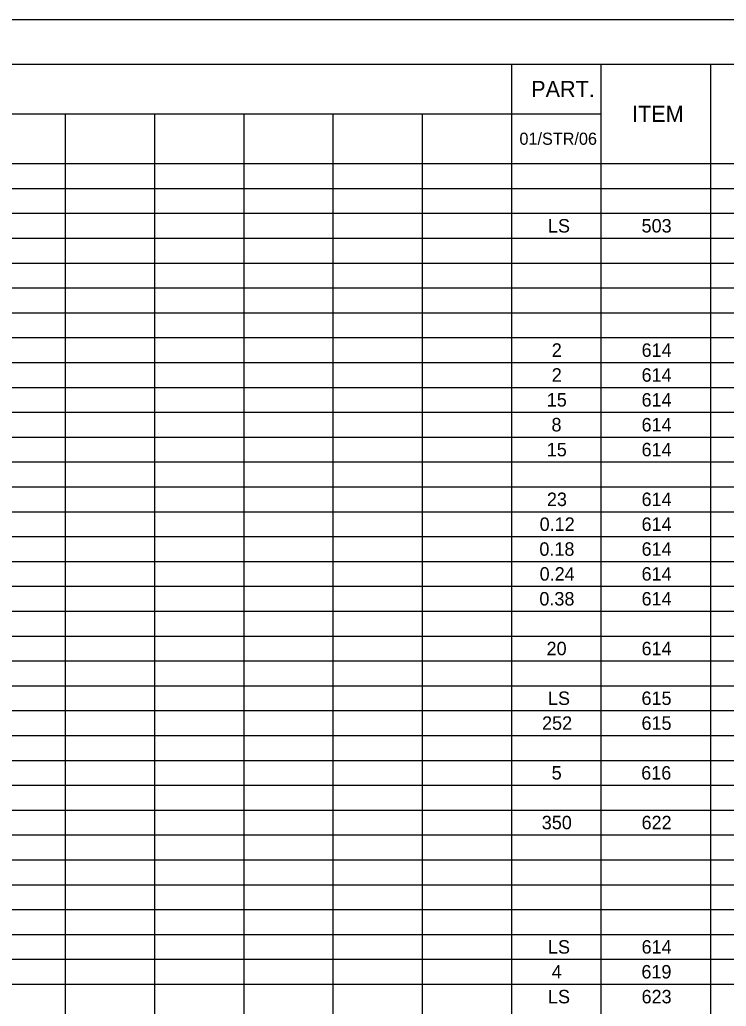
# Model space of a CAD drawing. Extents: x 0 to 34, y 0 to 22.
# Drawn here: x 9.03 to 16.97, y 10.89 to 22 of the extents above; entities that cross this region are included whole.
import ezdxf

# ---------------------------------------------------------------- set-up
doc = ezdxf.new("R2010")
doc.units = 0
for name, color, linetype in [('Default', 7, 'Continuous'), ('SH_Border', 7, 'Continuous'), ('SH_Cut_Line', 7, 'Continuous')]:
    doc.layers.add(name, color=color, linetype=linetype)

msp = doc.modelspace()

# ---------------------------------------------------------------- linework, layer by layer
at = {"layer": 'Default'}
for p, q in [((1.5, 21.5), (32, 21.5)), ((14.56, 21.5), (14.56, 0.5)), ((15.564, 21.5), (15.564, 0.5)), ((16.799, 21.5), (16.799, 0.5)), ((1.5, 20.94), (15.564, 20.94)), ((9.537, 20.94), (9.537, 0.5)), ((10.541, 20.94), (10.541, 0.5)), ((11.546, 20.94), (11.546, 0.5)), ((12.55, 20.94), (12.55, 0.5)), ((13.555, 20.94), (13.555, 0.5)), ((1.5, 20.38), (32, 20.38)), ((1.5, 20.1), (32, 20.1)), ((1.5, 19.82), (32, 19.82)), ((1.5, 19.54), (32, 19.54)), ((1.5, 19.26), (32, 19.26)), ((1.5, 18.98), (32, 18.98)), ((1.5, 18.7), (32, 18.7)), ((1.5, 18.42), (32, 18.42)), ((1.5, 18.14), (32, 18.14)), ((1.5, 17.86), (32, 17.86)), ((1.5, 17.58), (32, 17.58)), ((1.5, 17.3), (32, 17.3)), ((1.5, 17.02), (32, 17.02)), ((1.5, 16.74), (32, 16.74)), ((1.5, 16.46), (32, 16.46)), ((1.5, 16.18), (32, 16.18)), ((1.5, 15.9), (32, 15.9)), ((1.5, 15.62), (32, 15.62)), ((1.5, 15.34), (32, 15.34)), ((1.5, 15.06), (32, 15.06)), ((1.5, 14.78), (32, 14.78)), ((1.5, 14.5), (32, 14.5)), ((1.5, 14.22), (32, 14.22)), ((1.5, 13.94), (32, 13.94)), ((1.5, 13.66), (32, 13.66)), ((1.5, 13.38), (32, 13.38)), ((1.5, 13.1), (32, 13.1)), ((1.5, 12.82), (32, 12.82)), ((1.5, 12.54), (32, 12.54)), ((1.5, 12.26), (32, 12.26)), ((1.5, 11.98), (32, 11.98)), ((1.5, 11.7), (32, 11.7)), ((1.5, 11.42), (32, 11.42)), ((1.5, 11.14), (32, 11.14))]:
    msp.add_line(p, q, dxfattribs=at)
at = {"layer": 'SH_Border'}
msp.add_lwpolyline([(1.5, 21.5), (33.5, 21.5), (33.5, 0.5), (1.5, 0.5)], close=True, dxfattribs=at)
at = {"layer": 'SH_Cut_Line'}
msp.add_lwpolyline([(0, 0), (34, 0), (34, 22), (0, 22)], close=True, dxfattribs=at)

# ---------------------------------------------------------------- texts
at = {"layer": 'Default'}
for s, height, p in [('PART.', 0.1818, (14.78, 21.129)), ('ITEM', 0.1818, (15.915, 20.849)), ('01/STR/06', 0.1364, (14.648, 20.592)), ('LS', 0.1515, (14.969, 19.604)), ('503', 0.1515, (16.022, 19.604)), ('2', 0.152, (15.011, 18.204)), ('614', 0.1515, (16.022, 18.204)), ('2', 0.152, (15.011, 17.924)), ('614', 0.1515, (16.022, 17.924)), ('15', 0.1515, (14.955, 17.644)), ('614', 0.1515, (16.022, 17.644)), ('8', 0.152, (15.008, 17.364)), ('614', 0.1515, (16.022, 17.364)), ('15', 0.1515, (14.955, 17.084)), ('614', 0.1515, (16.022, 17.084)), ('23', 0.1515, (14.957, 16.524)), ('614', 0.1515, (16.022, 16.524)), ('0.12', 0.1515, (14.875, 16.244)), ('614', 0.1515, (16.022, 16.244)), ('0.18', 0.1515, (14.872, 15.964)), ('614', 0.1515, (16.022, 15.964)), ('0.24', 0.1515, (14.875, 15.684)), ('614', 0.1515, (16.022, 15.684)), ('0.38', 0.1515, (14.872, 15.404)), ('614', 0.1515, (16.022, 15.404)), ('20', 0.1515, (14.953, 14.844)), ('614', 0.1515, (16.022, 14.844)), ('LS', 0.1515, (14.969, 14.284)), ('615', 0.1515, (16.021, 14.284)), ('252', 0.1515, (14.902, 14.004)), ('615', 0.1515, (16.021, 14.004)), ('5', 0.152, (15.01, 13.444)), ('616', 0.1515, (16.018, 13.444)), ('350', 0.1515, (14.899, 12.884)), ('622', 0.1515, (16.022, 12.884)), ('LS', 0.1515, (14.969, 11.484)), ('614', 0.1515, (16.022, 11.484)), ('4', 0.152, (15.011, 11.204)), ('619', 0.1515, (16.02, 11.204)), ('LS', 0.1515, (14.969, 10.924)), ('623', 0.1515, (16.022, 10.924))]:
    msp.add_text(s, height=height, dxfattribs=at).set_placement(p)

doc.saveas('drawing.dxf')
